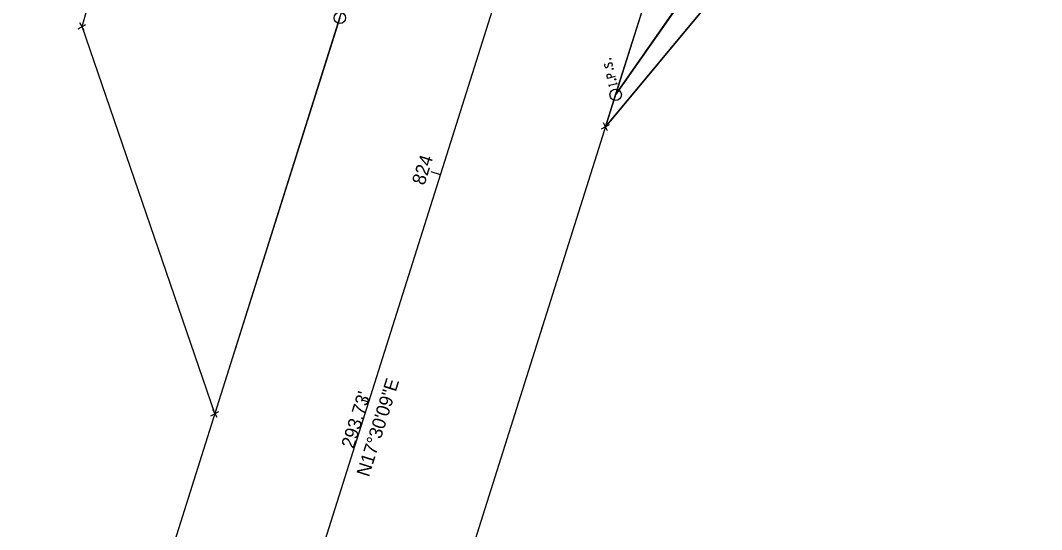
# Model space of a CAD drawing. Extents: x 2376935 to 2379466, y 252990 to 254108.
# Drawn here: x 2377907.9 to 2378122, y 253472.6 to 253579.4 of the extents above; entities that cross this region are included whole.
import ezdxf

# ---------------------------------------------------------------- set-up
doc = ezdxf.new("R2010")
doc.units = 0
for name, color, linetype in [('_CIVIL_CONSTRUCTION', 7, 'Continuous'), ('MD_P_Special_Benching_CheckPoint', 7, 'Continuous'), ('PF_X_Ground_Line', 7, 'Continuous'), ('SC_Scratch11', 7, 'Continuous'), ('SC_Scratch2', 7, 'Continuous'), ('SH_Border', 7, 'Continuous'), ('SH_Cut_Line', 7, 'Continuous'), ('SH_Data', 7, 'Continuous'), ('SN_X_Public', 7, 'Continuous'), ('UT_X_FO', 7, 'Continuous'), ('UT_X_Misc_Cells', 7, 'Continuous'), ('VG_P_Cells', 7, 'Continuous')]:
    doc.layers.add(name, color=color, linetype=linetype)

msp = doc.modelspace()

# ---------------------------------------------------------------- linework, layer by layer
at = {"layer": '_CIVIL_CONSTRUCTION'}
for p, q in [((2377995.97, 253547.03), (2377994.06, 253547.64)), ((2377980.93, 253499.35), (2377979.79, 253499.71))]:
    msp.add_line(p, q, dxfattribs=at)
at = {"layer": 'MD_P_Special_Benching_CheckPoint'}
for p, q in [((2378122, 253667.16), (2378030.6, 253557.09)), ((2378032.7, 253563.76), (2378098.71, 253658.38)), ((2377920.83, 253578.07), (2377941.78, 253651.15)), ((2377974.88, 253579.9), (2377948.71, 253496.93)), ((2377948.71, 253496.93), (2377920.83, 253578.07)), ((2378030.6, 253557.09), (2378032.7, 253563.76))]:
    msp.add_line(p, q, dxfattribs=at)
at = {"layer": 'PF_X_Ground_Line'}
for p, q in [((2377907.92, 253367.56), (2377995.3, 253644.64)), ((2377907.92, 253367.56), (2377995.3, 253644.64)), ((2377963.22, 253343.41), (2378052.52, 253626.6))]:
    msp.add_line(p, q, dxfattribs=at)
at = {"layer": 'SC_Scratch11'}
for p, q in [((2378098.71, 253658.38), (2378032.7, 253563.76)), ((2378032.7, 253563.76), (2378052.52, 253626.6))]:
    msp.add_line(p, q, dxfattribs=at)
at = {"layer": 'SH_Border'}
for p, q in [((2377920, 253577.62), (2377921.66, 253578.52)), ((2377921.28, 253577.24), (2377920.38, 253578.9)), ((2378029.76, 253556.66), (2378031.44, 253557.52)), ((2378031.03, 253556.25), (2378030.17, 253557.93)), ((2377947.87, 253496.5), (2377949.55, 253497.36)), ((2377949.14, 253496.09), (2377948.28, 253497.77))]:
    msp.add_line(p, q, dxfattribs=at)
at = {"layer": 'SH_Cut_Line'}
for points in [[(2378030.43, 253570.18), (2378030.41, 253570.15), (2378030.4, 253570.11), (2378030.38, 253570.01), (2378030.39, 253569.88), (2378030.41, 253569.8), (2378030.42, 253569.76), (2378030.49, 253569.63), (2378030.59, 253569.53), (2378030.71, 253569.48), (2378030.81, 253569.49), (2378030.88, 253569.5), (2378030.97, 253569.55), (2378031.04, 253569.66), (2378031.26, 253570.33), (2378031.3, 253570.4), (2378031.34, 253570.43), (2378031.41, 253570.47), (2378031.48, 253570.49), (2378031.56, 253570.5), (2378031.61, 253570.5), (2378031.68, 253570.49), (2378031.73, 253570.48), (2378031.77, 253570.47), (2378031.82, 253570.45), (2378031.85, 253570.42), (2378031.89, 253570.38), (2378031.91, 253570.35), (2378031.94, 253570.26), (2378031.98, 253570.11), (2378031.98, 253570.01), (2378031.93, 253569.85), (2378031.87, 253569.74)], [(2378031.48, 253571.27), (2378031.46, 253571.32), (2378031.48, 253571.36), (2378031.52, 253571.41), (2378031.58, 253571.42), (2378031.64, 253571.4), (2378031.67, 253571.37), (2378031.68, 253571.32), (2378031.67, 253571.28), (2378031.63, 253571.24), (2378031.57, 253571.22), (2378031.51, 253571.24), (2378031.48, 253571.27)], [(2378032.59, 253567.6), (2378031.03, 253567.23), (2378030.91, 253567.74), (2378030.91, 253567.8), (2378030.91, 253567.88), (2378030.93, 253567.92), (2378030.95, 253567.95), (2378031, 253568.01), (2378031.05, 253568.06), (2378031.14, 253568.1), (2378031.29, 253568.14), (2378031.34, 253568.14), (2378031.42, 253568.14), (2378031.52, 253568.12), (2378031.57, 253568.08), (2378031.6, 253568.06), (2378031.63, 253568.01), (2378031.67, 253567.92), (2378031.79, 253567.41)], [(2378031.99, 253569.15), (2378031.98, 253569.2), (2378032, 253569.24), (2378032.04, 253569.29), (2378032.1, 253569.3), (2378032.16, 253569.28), (2378032.19, 253569.25), (2378032.2, 253569.2), (2378032.18, 253569.16), (2378032.14, 253569.12), (2378032.08, 253569.1), (2378032.02, 253569.12), (2378031.99, 253569.15)], [(2378031.45, 253565.53), (2378031.36, 253565.88)], [(2378032.96, 253566.08), (2378031.4, 253565.71)], [(2378032.52, 253566.96), (2378032.51, 253567.02), (2378032.53, 253567.06), (2378032.57, 253567.1), (2378032.63, 253567.12), (2378032.69, 253567.1), (2378032.72, 253567.07), (2378032.73, 253567.02), (2378032.72, 253566.98), (2378032.67, 253566.93), (2378032.61, 253566.92), (2378032.56, 253566.94), (2378032.52, 253566.96)], [(2378033, 253565.91), (2378032.92, 253566.26)]]:
    msp.add_lwpolyline(points, dxfattribs=at)
for centre in [(2377974.88, 253579.9), (2378032.7, 253563.76)]:
    msp.add_circle(centre, 1.2, dxfattribs=at)
at = {"layer": 'SH_Data'}
msp.add_lwpolyline([(2378032.7, 253563.76), (2378098.71, 253658.38), (2378112.67, 253693.66), (2378060, 253741.78)], dxfattribs=at)
at = {"layer": 'UT_X_FO'}
msp.add_line((2377935.57, 253355.49), (2378023.91, 253635.62), dxfattribs=at)
at = {"layer": 'UT_X_Misc_Cells'}
msp.add_circle((2378017.29, 253514.89), 0.05, dxfattribs=at)
at = {"layer": 'VG_P_Cells'}
for p, q in [((2378030.6, 253557.09), (2378122, 253667.16)), ((2377920.83, 253578.07), (2377941.78, 253651.15)), ((2377948.71, 253496.93), (2377920.83, 253578.07))]:
    msp.add_line(p, q, dxfattribs=at)

# ---------------------------------------------------------------- texts
at = {"layer": '_CIVIL_CONSTRUCTION'}
msp.add_text('824', height=2.8, rotation=72.4976, dxfattribs=at).set_placement((2377992.6, 253544.66))
at = {"layer": 'SC_Scratch2'}
msp.add_text("293.73'", height=2.8, rotation=72.4976, dxfattribs=at).set_placement((2377977.77, 253489.43))
at = {"layer": 'SN_X_Public'}
msp.add_text('N17°30\'09"E', height=2.8, rotation=72.4976, dxfattribs=at).set_placement((2377980.97, 253483.51))

doc.saveas('drawing.dxf')
